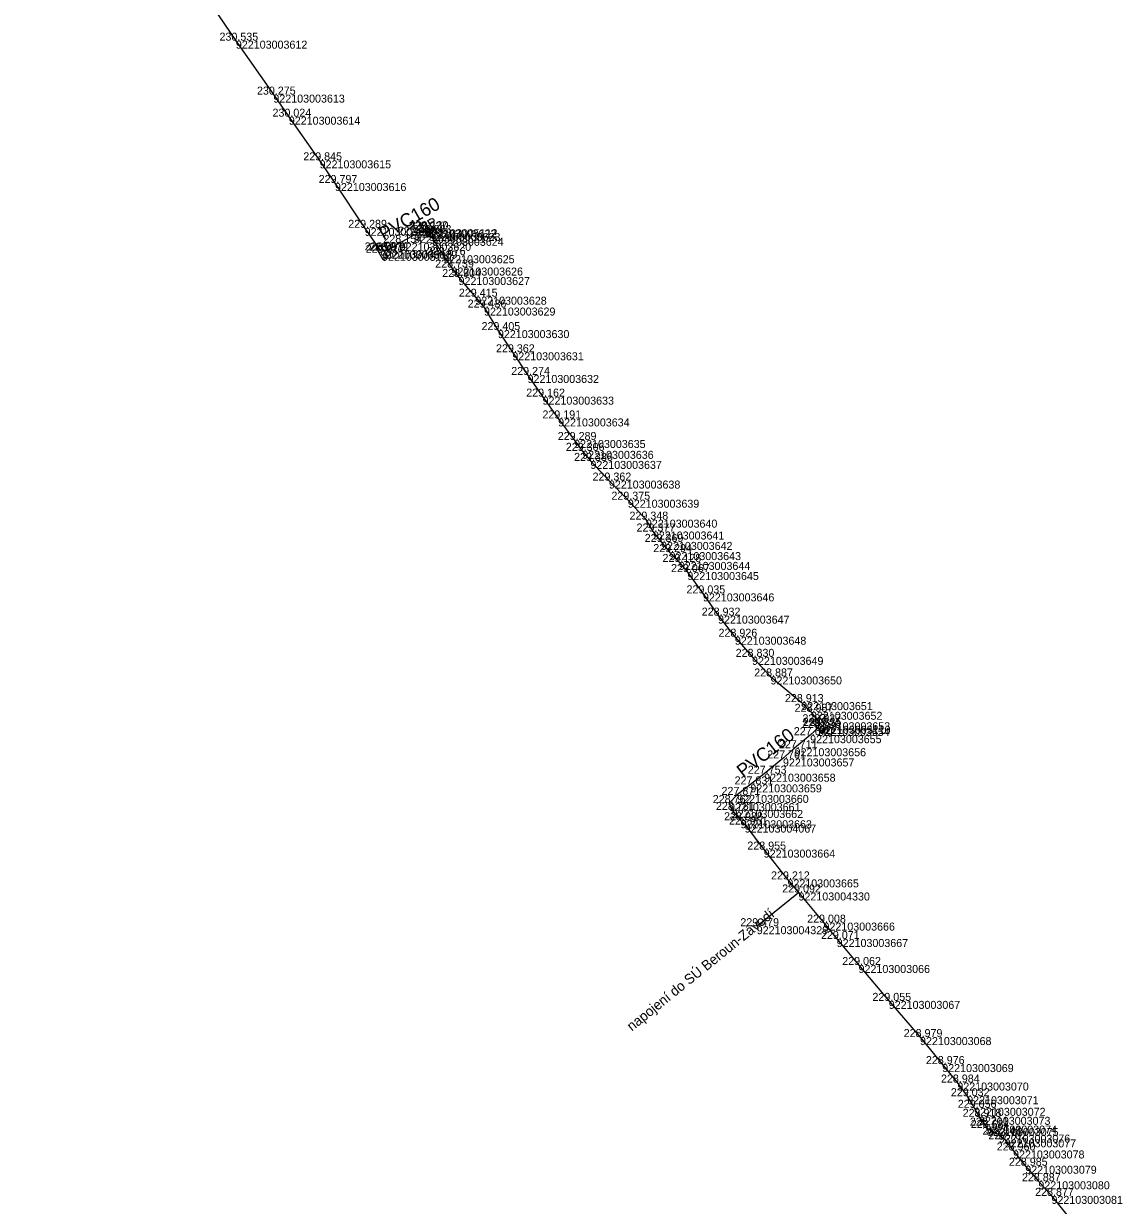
# Model space of a CAD drawing. Extents: x -771047 to -756200, y -1053876 to -1046520.
# Drawn here: x -768767.6 to -768602.9, y -1052954.8 to -1052777.6 of the extents above; entities that cross this region are included whole.
import ezdxf

# ---------------------------------------------------------------- set-up
doc = ezdxf.new("R2010")
doc.units = 0
for name, color, linetype in [('Vrstva 32', 7, 'Continuous'), ('Vrstva 33', 7, 'Continuous'), ('Vrstva 60', 7, 'Continuous'), ('Vrstva 61', 7, 'Continuous'), ('Vrstva 63', 7, 'Continuous')]:
    doc.layers.add(name, color=color, linetype=linetype)

msp = doc.modelspace()

# ---------------------------------------------------------------- linework, layer by layer
at = {"layer": 'Vrstva 32'}
for points in [[(-768767.63, -1052745.94), (-768765.03, -1052748.07), (-768763.32, -1052749.53), (-768760.7, -1052751.93), (-768758.82, -1052753.76), (-768758.36, -1052754.25), (-768756.84, -1052755.36), (-768756.33, -1052755.83), (-768755.66, -1052756.37), (-768755.17, -1052756.78), (-768753.45, -1052758.22), (-768750.61, -1052761.03), (-768747.89, -1052763.85), (-768746.55, -1052765.45), (-768742.89, -1052770.16), (-768739.33, -1052775.02), (-768735.8, -1052780.13), (-768730.18, -1052788.22), (-768727.86, -1052791.53), (-768723.24, -1052798.08), (-768720.94, -1052801.48), (-768716.49, -1052808.2), (-768714.14, -1052811.59)], [(-768714.14, -1052811.59), (-768713.34, -1052811.64), (-768711.23, -1052810.45), (-768709.06, -1052809.24), (-768707.44, -1052808.46), (-768706.84, -1052808.98)], [(-768706.84, -1052808.98), (-768706.36, -1052809.7), (-768704.71, -1052812.31), (-768703.46, -1052814.16), (-768702.41, -1052815.58), (-768699.9, -1052818.53), (-768698.59, -1052820.16), (-768696.5, -1052823.54), (-768694.34, -1052826.87), (-768692.06, -1052830.27), (-768689.81, -1052833.52), (-768687.47, -1052836.79), (-768685.07, -1052840.02), (-768683.86, -1052841.65), (-768682.63, -1052843.16), (-768679.86, -1052846.11), (-768677.02, -1052848.98), (-768674.31, -1052851.97), (-768673.26, -1052853.75), (-768672.04, -1052855.31), (-768670.76, -1052856.84), (-768669.37, -1052858.31), (-768668.09, -1052859.83), (-768665.76, -1052863.03), (-768663.49, -1052866.37), (-768660.97, -1052869.53), (-768658.4, -1052872.55), (-768655.62, -1052875.49), (-768651.01, -1052879.34), (-768649.56, -1052880.79), (-768648.39, -1052882.36)], [(-768648.39, -1052882.36), (-768648.46, -1052883.2), (-768649.68, -1052884.3), (-768652.01, -1052886.26), (-768653.76, -1052887.79), (-768656.58, -1052890.08), (-768658.65, -1052891.68), (-768660.61, -1052893.26), (-768661.84, -1052894.48)], [(-768661.84, -1052894.48), (-768661.45, -1052895.52), (-768660.13, -1052897.06), (-768659.49, -1052897.71), (-768656.64, -1052901.46), (-768653.09, -1052905.93), (-768651.43, -1052907.89), (-768647.68, -1052912.42), (-768645.7, -1052914.87)], [(-768657.69, -1052912.95), (-768651.43, -1052907.89)], [(-768645.7, -1052914.87), (-768642.42, -1052918.77), (-768637.89, -1052924.15), (-768633.2, -1052929.58), (-768629.87, -1052933.63), (-768627.61, -1052936.4), (-768626.13, -1052938.45), (-768625.09, -1052940.19), (-768624.36, -1052941.54), (-768623.37, -1052942.86), (-768623.14, -1052943.22), (-768621.39, -1052944.21), (-768620.5, -1052944.92), (-768619.25, -1052946.59), (-768617.42, -1052948.88), (-768615.46, -1052951.21), (-768613.49, -1052953.4), (-768611.21, -1052956.25)]]:
    msp.add_lwpolyline(points, dxfattribs=at)
at = {"layer": 'Vrstva 33'}
for points in [[(-768708.1, -1052807.72), (-768707.46, -1052807.35), (-768706.46, -1052809.1), (-768707.11, -1052809.47)], [(-768714.7, -1052811.26), (-768714.05, -1052810.89), (-768713.06, -1052812.64), (-768713.71, -1052813.01)], [(-768649.29, -1052882.4), (-768648.74, -1052881.9), (-768647.39, -1052883.4), (-768647.94, -1052883.89)]]:
    msp.add_lwpolyline(points, close=True, dxfattribs=at)
for points in [[(-768707, -1052807.09), (-768706.55, -1052806.83)], [(-768706.39, -1052808.18), (-768707, -1052807.09)], [(-768706.25, -1052807.37), (-768706.7, -1052807.63)], [(-768706.55, -1052806.83), (-768706.39, -1052806.8), (-768706.19, -1052806.92), (-768706.14, -1052807.02), (-768706.13, -1052807.25), (-768706.25, -1052807.37)], [(-768714.14, -1052811.59), (-768713.34, -1052811.64), (-768711.23, -1052810.45), (-768709.06, -1052809.24), (-768707.44, -1052808.46), (-768706.84, -1052808.98)], [(-768713.6, -1052810.63), (-768713.15, -1052810.37)], [(-768712.98, -1052811.72), (-768713.6, -1052810.63)], [(-768712.84, -1052810.91), (-768713.29, -1052811.17)], [(-768713.15, -1052810.37), (-768712.98, -1052810.34), (-768712.79, -1052810.46), (-768712.73, -1052810.56), (-768712.73, -1052810.8), (-768712.84, -1052810.91)], [(-768648.39, -1052882.36), (-768648.46, -1052883.2), (-768649.68, -1052884.3), (-768652.01, -1052886.26), (-768653.76, -1052887.79), (-768656.58, -1052890.08), (-768658.65, -1052891.68), (-768660.61, -1052893.26), (-768661.84, -1052894.48)], [(-768648.35, -1052881.55), (-768647.96, -1052881.2)], [(-768647.51, -1052882.48), (-768648.35, -1052881.55)], [(-768647.96, -1052881.2), (-768647.81, -1052881.13), (-768647.59, -1052881.21), (-768647.52, -1052881.29), (-768647.46, -1052881.52), (-768647.55, -1052881.66)], [(-768647.55, -1052881.66), (-768647.94, -1052882.01)]]:
    msp.add_lwpolyline(points, dxfattribs=at)
at = {"layer": 'Vrstva 60'}
for p, q in [((-768735.8, -1052780.13), (-768735.8, -1052780.13)), ((-768730.18, -1052788.22), (-768730.18, -1052788.22)), ((-768727.86, -1052791.53), (-768727.86, -1052791.53)), ((-768723.24, -1052798.08), (-768723.24, -1052798.08)), ((-768720.94, -1052801.48), (-768720.94, -1052801.48)), ((-768716.49, -1052808.2), (-768716.49, -1052808.2)), ((-768709.06, -1052809.24), (-768709.06, -1052809.24)), ((-768707.44, -1052808.46), (-768707.44, -1052808.46)), ((-768707.28, -1052808.41), (-768707.28, -1052808.41)), ((-768706.84, -1052808.98), (-768706.84, -1052808.98)), ((-768706.36, -1052809.7), (-768706.36, -1052809.7)), ((-768714.14, -1052811.59), (-768714.14, -1052811.59)), ((-768713.34, -1052811.64), (-768713.34, -1052811.64)), ((-768711.23, -1052810.45), (-768711.23, -1052810.45)), ((-768713.88, -1052811.95), (-768713.88, -1052811.95)), ((-768704.71, -1052812.31), (-768704.71, -1052812.31)), ((-768703.46, -1052814.16), (-768703.46, -1052814.16)), ((-768702.41, -1052815.58), (-768702.41, -1052815.58)), ((-768699.9, -1052818.53), (-768699.9, -1052818.53)), ((-768698.59, -1052820.16), (-768698.59, -1052820.16)), ((-768696.5, -1052823.54), (-768696.5, -1052823.54)), ((-768694.34, -1052826.87), (-768694.34, -1052826.87)), ((-768692.06, -1052830.27), (-768692.06, -1052830.27)), ((-768689.81, -1052833.52), (-768689.81, -1052833.52)), ((-768687.47, -1052836.79), (-768687.47, -1052836.79)), ((-768685.07, -1052840.02), (-768685.07, -1052840.02)), ((-768683.86, -1052841.65), (-768683.86, -1052841.65)), ((-768682.63, -1052843.16), (-768682.63, -1052843.16)), ((-768679.86, -1052846.11), (-768679.86, -1052846.11)), ((-768677.02, -1052848.98), (-768677.02, -1052848.98)), ((-768674.31, -1052851.97), (-768674.31, -1052851.97)), ((-768673.26, -1052853.75), (-768673.26, -1052853.75)), ((-768672.04, -1052855.31), (-768672.04, -1052855.31)), ((-768670.76, -1052856.84), (-768670.76, -1052856.84)), ((-768669.37, -1052858.31), (-768669.37, -1052858.31)), ((-768668.09, -1052859.83), (-768668.09, -1052859.83)), ((-768665.76, -1052863.03), (-768665.76, -1052863.03)), ((-768663.49, -1052866.37), (-768663.49, -1052866.37)), ((-768660.97, -1052869.53), (-768660.97, -1052869.53)), ((-768658.4, -1052872.55), (-768658.4, -1052872.55)), ((-768655.62, -1052875.49), (-768655.62, -1052875.49)), ((-768651.01, -1052879.34), (-768651.01, -1052879.34)), ((-768649.56, -1052880.79), (-768649.56, -1052880.79)), ((-768648.39, -1052882.36), (-768648.39, -1052882.36)), ((-768649.68, -1052884.3), (-768649.68, -1052884.3)), ((-768648.46, -1052883.2), (-768648.46, -1052883.2)), ((-768648.34, -1052882.9), (-768648.34, -1052882.9)), ((-768653.76, -1052887.79), (-768653.76, -1052887.79)), ((-768652.01, -1052886.26), (-768652.01, -1052886.26)), ((-768656.58, -1052890.08), (-768656.58, -1052890.08)), ((-768660.61, -1052893.26), (-768660.61, -1052893.26)), ((-768658.65, -1052891.68), (-768658.65, -1052891.68)), ((-768661.84, -1052894.48), (-768661.84, -1052894.48)), ((-768661.45, -1052895.52), (-768661.45, -1052895.52)), ((-768660.13, -1052897.06), (-768660.13, -1052897.06)), ((-768659.49, -1052897.71), (-768659.49, -1052897.71)), ((-768656.64, -1052901.46), (-768656.64, -1052901.46)), ((-768653.09, -1052905.93), (-768653.09, -1052905.93)), ((-768651.43, -1052907.89), (-768651.43, -1052907.89)), ((-768647.68, -1052912.42), (-768647.68, -1052912.42)), ((-768657.69, -1052912.95), (-768657.69, -1052912.95)), ((-768645.7, -1052914.87), (-768645.7, -1052914.87)), ((-768642.42, -1052918.77), (-768642.42, -1052918.77)), ((-768637.89, -1052924.15), (-768637.89, -1052924.15)), ((-768633.2, -1052929.58), (-768633.2, -1052929.58)), ((-768629.87, -1052933.63), (-768629.87, -1052933.63)), ((-768627.61, -1052936.4), (-768627.61, -1052936.4)), ((-768626.13, -1052938.45), (-768626.13, -1052938.45)), ((-768625.09, -1052940.19), (-768625.09, -1052940.19)), ((-768624.36, -1052941.54), (-768624.36, -1052941.54)), ((-768623.37, -1052942.86), (-768623.37, -1052942.86)), ((-768623.14, -1052943.22), (-768623.14, -1052943.22)), ((-768621.39, -1052944.21), (-768621.39, -1052944.21)), ((-768620.5, -1052944.92), (-768620.5, -1052944.92)), ((-768619.25, -1052946.59), (-768619.25, -1052946.59)), ((-768617.42, -1052948.88), (-768617.42, -1052948.88)), ((-768615.46, -1052951.21), (-768615.46, -1052951.21)), ((-768613.49, -1052953.4), (-768613.49, -1052953.4))]:
    msp.add_line(p, q, dxfattribs=at)

# ---------------------------------------------------------------- texts
at = {"layer": 'Vrstva 33'}
for rotation, p in [(29.4902, (-768713.65, -1052810.13)), (37.7714, (-768659.72, -1052890.75))]:
    msp.add_text('PVC160', height=2, rotation=rotation, dxfattribs=at).set_placement(p)
at = {"layer": 'Vrstva 60'}
for s, p in [('922103003612', (-768735.8, -1052781.33)), ('922103003613', (-768730.18, -1052789.42)), ('922103003614', (-768727.86, -1052792.73)), ('922103003615', (-768723.24, -1052799.28)), ('922103003616', (-768720.94, -1052802.68)), ('922103003617', (-768716.49, -1052809.4)), ('922103003621', (-768709.06, -1052810.44)), ('922103003622', (-768707.44, -1052809.66)), ('922103005112', (-768707.28, -1052809.61)), ('922103003623', (-768706.84, -1052810.18)), ('922103003624', (-768706.36, -1052810.9)), ('922103003618', (-768714.14, -1052812.79)), ('922103003619', (-768713.34, -1052812.84)), ('922103003620', (-768711.23, -1052811.65)), ('922103005111', (-768713.88, -1052813.15)), ('922103003625', (-768704.71, -1052813.51)), ('922103003626', (-768703.46, -1052815.36)), ('922103003627', (-768702.41, -1052816.78)), ('922103003628', (-768699.9, -1052819.73)), ('922103003629', (-768698.59, -1052821.36)), ('922103003630', (-768696.5, -1052824.74)), ('922103003631', (-768694.34, -1052828.07)), ('922103003632', (-768692.06, -1052831.47)), ('922103003633', (-768689.81, -1052834.72)), ('922103003634', (-768687.47, -1052837.99)), ('922103003635', (-768685.07, -1052841.22)), ('922103003636', (-768683.86, -1052842.85)), ('922103003637', (-768682.63, -1052844.36)), ('922103003638', (-768679.86, -1052847.31)), ('922103003639', (-768677.02, -1052850.18)), ('922103003640', (-768674.31, -1052853.17)), ('922103003641', (-768673.26, -1052854.95)), ('922103003642', (-768672.04, -1052856.51)), ('922103003643', (-768670.76, -1052858.04)), ('922103003644', (-768669.37, -1052859.51)), ('922103003645', (-768668.09, -1052861.03)), ('922103003646', (-768665.76, -1052864.23)), ('922103003647', (-768663.49, -1052867.57)), ('922103003648', (-768660.97, -1052870.73)), ('922103003649', (-768658.4, -1052873.75)), ('922103003650', (-768655.62, -1052876.69)), ('922103003651', (-768651.01, -1052880.54)), ('922103003652', (-768649.56, -1052881.99)), ('922103003653', (-768648.39, -1052883.56)), ('922103003655', (-768649.68, -1052885.5)), ('922103003654', (-768648.46, -1052884.4)), ('922103005110', (-768648.34, -1052884.1)), ('922103003657', (-768653.76, -1052888.99)), ('922103003656', (-768652.01, -1052887.46)), ('922103003658', (-768656.58, -1052891.28)), ('922103003660', (-768660.61, -1052894.46)), ('922103003659', (-768658.65, -1052892.88)), ('922103003661', (-768661.84, -1052895.68)), ('922103003662', (-768661.45, -1052896.72)), ('922103003663', (-768660.13, -1052898.26)), ('922103004067', (-768659.49, -1052898.91)), ('922103003664', (-768656.64, -1052902.66)), ('922103003665', (-768653.09, -1052907.13)), ('922103004330', (-768651.43, -1052909.09)), ('922103003666', (-768647.68, -1052913.61)), ('922103004329', (-768657.69, -1052914.15)), ('922103003667', (-768645.7, -1052916.07)), ('922103003066', (-768642.42, -1052919.97)), ('922103003067', (-768637.89, -1052925.35)), ('922103003068', (-768633.2, -1052930.78)), ('922103003069', (-768629.87, -1052934.83)), ('922103003070', (-768627.61, -1052937.6)), ('922103003071', (-768626.13, -1052939.65)), ('922103003072', (-768625.09, -1052941.39)), ('922103003073', (-768624.36, -1052942.74)), ('922103003074', (-768623.37, -1052944.06)), ('922103003075', (-768623.14, -1052944.42)), ('922103003076', (-768621.39, -1052945.41)), ('922103003077', (-768620.5, -1052946.12)), ('922103003078', (-768619.25, -1052947.79)), ('922103003079', (-768617.42, -1052950.08)), ('922103003080', (-768615.46, -1052952.41)), ('922103003081', (-768613.49, -1052954.6))]:
    msp.add_text(s, height=1.2, dxfattribs=at).set_placement(p)
at = {"layer": 'Vrstva 61'}
for s, p in [('230.535', (-768738.26, -1052780.13)), ('230.275', (-768732.64, -1052788.22)), ('230.024', (-768730.31, -1052791.53)), ('229.845', (-768725.69, -1052798.08)), ('229.797', (-768723.39, -1052801.48)), ('229.289', (-768718.95, -1052808.2)), ('227.925', (-768711.51, -1052809.24)), ('228.227', (-768709.89, -1052808.46)), ('229.130', (-768709.73, -1052808.41)), ('228.283', (-768709.29, -1052808.98)), ('228.154', (-768713.68, -1052810.45)), ('228.422', (-768708.81, -1052809.7)), ('228.991', (-768716.49, -1052811.59)), ('229.917', (-768716.33, -1052811.95)), ('228.979', (-768715.8, -1052811.64)), ('228.676', (-768707.16, -1052812.31)), ('228.739', (-768705.91, -1052814.16)), ('228.904', (-768704.86, -1052815.58)), ('229.415', (-768702.36, -1052818.53)), ('229.436', (-768701.04, -1052820.16)), ('229.405', (-768698.96, -1052823.54)), ('229.362', (-768696.79, -1052826.87)), ('229.274', (-768694.51, -1052830.27)), ('229.162', (-768692.26, -1052833.52)), ('229.191', (-768689.83, -1052836.79)), ('229.289', (-768687.53, -1052840.02)), ('229.306', (-768686.32, -1052841.65)), ('229.386', (-768685.08, -1052843.16)), ('229.362', (-768682.31, -1052846.11)), ('229.375', (-768679.48, -1052848.98)), ('229.348', (-768676.77, -1052851.97)), ('229.377', (-768675.71, -1052853.75)), ('229.369', (-768674.49, -1052855.31)), ('229.294', (-768673.21, -1052856.84)), ('229.128', (-768671.82, -1052858.31)), ('229.067', (-768670.54, -1052859.83)), ('229.035', (-768668.22, -1052863.03)), ('228.932', (-768665.94, -1052866.37)), ('228.926', (-768663.42, -1052869.53)), ('228.830', (-768660.85, -1052872.55)), ('228.887', (-768658.07, -1052875.49)), ('228.913', (-768653.46, -1052879.34)), ('228.987', (-768652.01, -1052880.79)), ('228.726', (-768650.91, -1052883.2)), ('228.937', (-768650.84, -1052882.36)), ('229.835', (-768650.79, -1052882.9)), ('227.640', (-768652.13, -1052884.3)), ('227.711', (-768654.37, -1052886.26)), ('227.761', (-768656.12, -1052887.79)), ('227.753', (-768659.03, -1052890.08)), ('227.831', (-768661.01, -1052891.68)), ('228.762', (-768664.29, -1052894.48)), ('227.871', (-768662.97, -1052893.26)), ('228.781', (-768663.81, -1052895.52)), ('228.938', (-768662.58, -1052897.06)), ('228.951', (-768661.85, -1052897.71)), ('228.955', (-768659.1, -1052901.46)), ('229.212', (-768655.54, -1052905.93)), ('229.092', (-768653.87, -1052907.89)), ('229.479', (-768660.15, -1052912.95)), ('229.008', (-768650.13, -1052912.42)), ('229.071', (-768648.06, -1052914.87)), ('229.062', (-768644.87, -1052918.77)), ('229.055', (-768640.34, -1052924.15)), ('228.979', (-768635.65, -1052929.58)), ('228.976', (-768632.32, -1052933.63)), ('228.984', (-768630.06, -1052936.4)), ('229.032', (-768628.58, -1052938.45)), ('229.056', (-768627.54, -1052940.19)), ('228.918', (-768626.81, -1052941.54)), ('228.701', (-768625.73, -1052942.86)), ('228.684', (-768625.59, -1052943.22)), ('228.548', (-768623.84, -1052944.21)), ('228.702', (-768622.95, -1052944.92)), ('228.960', (-768621.7, -1052946.59)), ('228.985', (-768619.87, -1052948.88)), ('228.887', (-768617.92, -1052951.21)), ('228.877', (-768615.94, -1052953.4))]:
    msp.add_text(s, height=1.2, dxfattribs=at).set_placement(p)
at = {"layer": 'Vrstva 63'}
msp.add_text('napojení do SÚ Beroun-Závodí', height=1.5, rotation=38.9168, dxfattribs=at).set_placement((-768676.42, -1052928.76))

doc.saveas('drawing.dxf')
